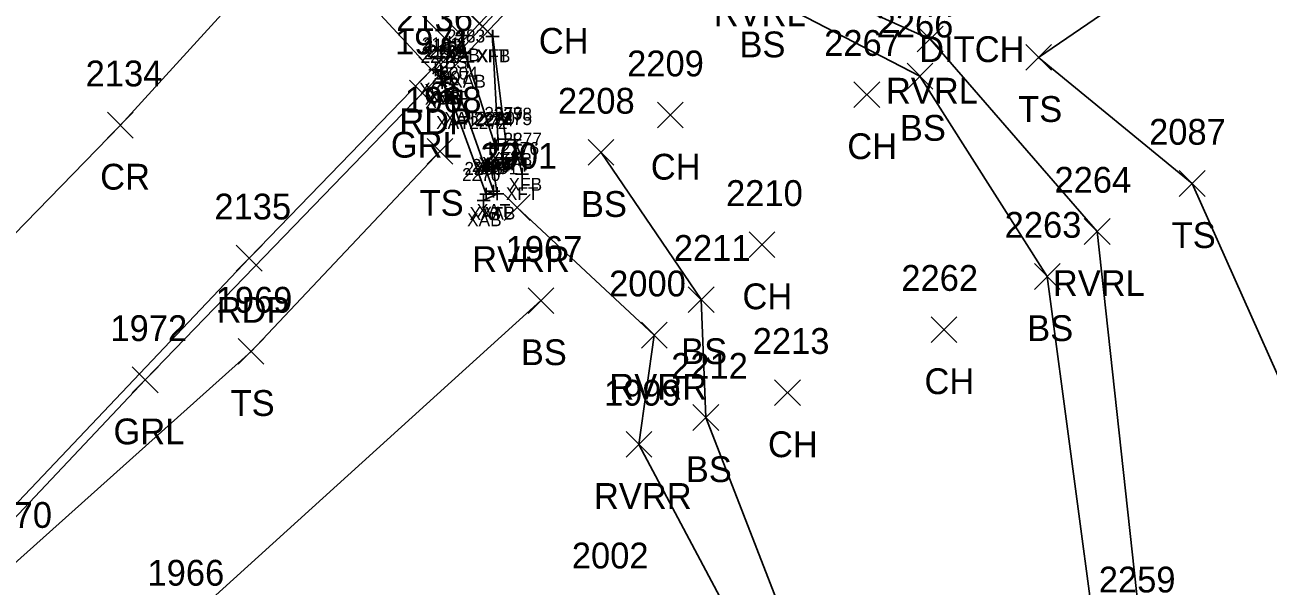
# Model space of a CAD drawing. Extents: x 1633660 to 1636532, y 388643 to 392631.
# Drawn here: x 1634731.9 to 1634828.3, y 389178.4 to 389221.9 of the extents above; entities that cross this region are included whole.
import ezdxf

# ---------------------------------------------------------------- set-up
doc = ezdxf.new("R2010")
doc.units = 0
for name, color, linetype in [('B_A', 7, 'Continuous'), ('B_I', 7, 'Continuous'), ('B_TIC', 7, 'Continuous'), ('BDC', 7, 'Continuous'), ('BFT', 7, 'Continuous'), ('BSE', 7, 'Continuous'), ('BSUBM', 7, 'Continuous'), ('D_A', 7, 'Continuous'), ('L_A', 7, 'Continuous'), ('L_I', 7, 'Continuous'), ('L_TIC', 7, 'Continuous'), ('LAWE', 7, 'Continuous'), ('LELB', 7, 'Continuous'), ('P_A', 7, 'Continuous'), ('P_I', 7, 'Continuous'), ('P_TIC', 7, 'Continuous'), ('PET', 7, 'Continuous'), ('PRC', 7, 'Continuous'), ('R_A', 7, 'Continuous'), ('R_I', 7, 'Continuous'), ('R_TIC', 7, 'Continuous'), ('RGR', 7, 'Continuous')]:
    doc.layers.add(name, color=color, linetype=linetype)

msp = doc.modelspace()

# ---------------------------------------------------------------- linework, layer by layer
at = {"layer": 'B_TIC'}
for p, q in [((1634764.83, 389220.538), (1634764.905, 389220.538)), ((1634765.792, 389221.095), (1634765.867, 389221.095)), ((1634768.164, 389221.033), (1634768.24, 389221.033)), ((1634768.201, 389221.026), (1634768.277, 389221.026)), ((1634763.743, 389218.447), (1634763.818, 389218.447)), ((1634764.167, 389218.344), (1634764.242, 389218.344)), ((1634766.258, 389219.061), (1634766.334, 389219.061)), ((1634764.198, 389217.752), (1634764.273, 389217.752)), ((1634764.265, 389217.48), (1634764.34, 389217.48)), ((1634764.459, 389217.898), (1634764.534, 389217.898)), ((1634764.903, 389217.804), (1634764.979, 389217.804)), ((1634765.097, 389215.857), (1634765.173, 389215.857)), ((1634765.728, 389216.186), (1634765.804, 389216.186)), ((1634768.359, 389212.667), (1634768.434, 389212.667)), ((1634768.466, 389212.553), (1634768.541, 389212.553)), ((1634768.609, 389212.698), (1634768.685, 389212.698)), ((1634769.173, 389213.071), (1634769.249, 389213.071)), ((1634769.889, 389213.007), (1634769.964, 389213.007)), ((1634769.892, 389212.659), (1634769.967, 389212.659)), ((1634767.992, 389212.36), (1634768.067, 389212.36)), ((1634770.659, 389211.073), (1634770.734, 389211.073)), ((1634770.466, 389210.348), (1634770.542, 389210.348)), ((1634767.69, 389208.805), (1634767.766, 389208.805)), ((1634768.245, 389209.038), (1634768.321, 389209.038)), ((1634768.538, 389208.841), (1634768.614, 389208.841)), ((1634767.482, 389208.325), (1634767.558, 389208.325))]:
    msp.add_line(p, q, dxfattribs=at)
for points in [[(1634765.788, 389220.595), (1634765.788, 389221.595)], [(1634768.161, 389220.533), (1634768.161, 389221.533)], [(1634768.198, 389220.526), (1634768.198, 389221.526)], [(1634764.326, 389220.538), (1634765.326, 389220.538)], [(1634764.826, 389220.038), (1634764.826, 389221.038)], [(1634765.288, 389221.095), (1634766.288, 389221.095)], [(1634767.661, 389221.033), (1634768.661, 389221.033)], [(1634767.698, 389221.026), (1634768.698, 389221.026)], [(1634766.255, 389218.561), (1634766.255, 389219.561)], [(1634763.24, 389218.447), (1634764.24, 389218.447)], [(1634763.663, 389218.344), (1634764.663, 389218.344)], [(1634763.74, 389217.947), (1634763.74, 389218.947)], [(1634764.163, 389217.844), (1634764.163, 389218.844)], [(1634764.455, 389217.398), (1634764.455, 389218.398)], [(1634765.755, 389219.061), (1634766.755, 389219.061)], [(1634763.694, 389217.752), (1634764.694, 389217.752)], [(1634763.761, 389217.48), (1634764.761, 389217.48)], [(1634763.955, 389217.898), (1634764.955, 389217.898)], [(1634764.194, 389217.252), (1634764.194, 389218.252)], [(1634764.261, 389216.98), (1634764.261, 389217.98)], [(1634764.4, 389217.804), (1634765.4, 389217.804)], [(1634764.9, 389217.304), (1634764.9, 389218.304)], [(1634765.725, 389215.686), (1634765.725, 389216.686)], [(1634764.594, 389215.857), (1634765.594, 389215.857)], [(1634765.094, 389215.357), (1634765.094, 389216.357)], [(1634765.225, 389216.186), (1634766.225, 389216.186)], [(1634769.17, 389212.571), (1634769.17, 389213.571)], [(1634767.855, 389212.667), (1634768.855, 389212.667)], [(1634767.962, 389212.553), (1634768.962, 389212.553)], [(1634767.988, 389211.86), (1634767.988, 389212.86)], [(1634768.106, 389212.698), (1634769.106, 389212.698)], [(1634768.355, 389212.167), (1634768.355, 389213.167)], [(1634768.462, 389212.053), (1634768.462, 389213.053)], [(1634768.606, 389212.198), (1634768.606, 389213.198)], [(1634768.67, 389213.071), (1634769.67, 389213.071)], [(1634769.385, 389213.007), (1634770.385, 389213.007)], [(1634769.388, 389212.659), (1634770.388, 389212.659)], [(1634769.885, 389212.507), (1634769.885, 389213.507)], [(1634769.888, 389212.158), (1634769.888, 389213.159)], [(1634767.488, 389212.36), (1634768.488, 389212.36)], [(1634770.155, 389211.073), (1634771.155, 389211.073)], [(1634770.463, 389209.848), (1634770.463, 389210.848)], [(1634770.655, 389210.573), (1634770.655, 389211.573)], [(1634769.963, 389210.348), (1634770.963, 389210.348)], [(1634767.187, 389208.805), (1634768.187, 389208.805)], [(1634767.479, 389207.825), (1634767.479, 389208.825)], [(1634767.687, 389208.305), (1634767.687, 389209.305)], [(1634767.742, 389209.038), (1634768.742, 389209.038)], [(1634768.035, 389208.841), (1634769.035, 389208.841)], [(1634768.242, 389208.538), (1634768.242, 389209.538)], [(1634768.535, 389208.341), (1634768.535, 389209.341)], [(1634766.979, 389208.325), (1634767.979, 389208.325)]]:
    msp.add_lwpolyline(points, dxfattribs=at)
at = {"layer": 'BDC'}
for points in [[(1634764.194, 389217.752), (1634763.74, 389218.447), (1634778.837, 389234.337), (1634779.352, 389233.631)], [(1634779.312, 389233.554), (1634778.858, 389234.061), (1634764.163, 389218.344), (1634764.455, 389217.898)], [(1634764.455, 389217.898), (1634779.312, 389233.554)]]:
    msp.add_lwpolyline(points, dxfattribs=at)
at = {"layer": 'BFT'}
for points in [[(1634746.993, 389241.835), (1634768.161, 389221.033)], [(1634747.068, 389242.136), (1634768.198, 389221.026)], [(1634768.606, 389212.698), (1634768.161, 389221.033)], [(1634770.655, 389211.073), (1634769.885, 389213.007), (1634769.17, 389213.071), (1634768.198, 389221.026)], [(1634768.462, 389212.553), (1634769.888, 389212.659), (1634770.463, 389210.348)]]:
    msp.add_lwpolyline(points, dxfattribs=at)
at = {"layer": 'BSE'}
msp.add_lwpolyline([(1634764.826, 389220.538), (1634746.059, 389239.297), (1634742.923, 389241.263)], dxfattribs=at)
at = {"layer": 'BSUBM'}
for points in [[(1634728.916, 389249.02), (1634729.836, 389250.104), (1634742.136, 389242.622), (1634746.673, 389240.04), (1634765.788, 389221.095)], [(1634765.788, 389221.095), (1634766.255, 389219.061)], [(1634767.479, 389208.325), (1634768.535, 389208.841), (1634767.988, 389212.36), (1634768.355, 389212.667), (1634766.255, 389219.061)], [(1634764.261, 389217.48), (1634764.9, 389217.804), (1634765.725, 389216.186), (1634768.242, 389209.038), (1634767.687, 389208.805), (1634765.094, 389215.857)], [(1634765.094, 389215.857), (1634764.261, 389217.48)]]:
    msp.add_lwpolyline(points, dxfattribs=at)
at = {"layer": 'L_TIC'}
for points in [[(1634801.108, 389219.823), (1634803.108, 389221.823)], [(1634803.108, 389219.823), (1634801.108, 389221.823)], [(1634809.516, 389218.404), (1634811.516, 389220.404)], [(1634811.516, 389218.404), (1634809.516, 389220.404)], [(1634800.315, 389216.947), (1634802.315, 389218.947)], [(1634802.315, 389216.947), (1634800.315, 389218.947)], [(1634796.191, 389215.523), (1634798.191, 389217.523)], [(1634798.191, 389215.523), (1634796.191, 389217.523)], [(1634780.954, 389213.935), (1634782.954, 389215.935)], [(1634782.954, 389213.935), (1634780.954, 389215.935)], [(1634763.106, 389211.132), (1634765.106, 389213.132)], [(1634765.106, 389211.132), (1634763.106, 389213.132)], [(1634775.585, 389211.045), (1634777.585, 389213.045)], [(1634777.585, 389211.045), (1634775.585, 389213.045)], [(1634821.419, 389208.639), (1634823.419, 389210.639)], [(1634823.419, 389208.639), (1634821.419, 389210.639)], [(1634769.084, 389206.774), (1634771.084, 389208.774)], [(1634771.084, 389206.774), (1634769.084, 389208.774)], [(1634814.049, 389204.919), (1634816.049, 389206.919)], [(1634816.049, 389204.919), (1634814.049, 389206.919)], [(1634788.059, 389203.893), (1634790.059, 389205.893)], [(1634790.059, 389203.893), (1634788.059, 389205.893)], [(1634810.187, 389201.43), (1634812.187, 389203.43)], [(1634812.187, 389201.43), (1634810.187, 389203.43)], [(1634770.923, 389199.563), (1634772.923, 389201.563)], [(1634772.923, 389199.563), (1634770.923, 389201.563)], [(1634783.352, 389199.641), (1634785.352, 389201.641)], [(1634785.352, 389199.641), (1634783.352, 389201.641)], [(1634802.174, 389197.318), (1634804.174, 389199.318)], [(1634804.174, 389197.318), (1634802.174, 389199.318)], [(1634779.716, 389196.887), (1634781.716, 389198.887)], [(1634781.716, 389196.887), (1634779.716, 389198.887)], [(1634748.452, 389195.628), (1634750.452, 389197.628)], [(1634750.452, 389195.628), (1634748.452, 389197.628)], [(1634790.04, 389192.433), (1634792.04, 389194.433)], [(1634792.04, 389192.433), (1634790.04, 389194.433)], [(1634783.715, 389190.503), (1634785.715, 389192.503)], [(1634785.715, 389190.503), (1634783.715, 389192.503)], [(1634778.524, 389188.425), (1634780.524, 389190.425)], [(1634780.524, 389188.425), (1634778.524, 389190.425)]]:
    msp.add_lwpolyline(points, dxfattribs=at)
at = {"layer": 'LAWE'}
for points in [[(1634485.266, 388945.868), (1634504.196, 388941.237), (1634525.532, 388940.734), (1634548.507, 388932.941), (1634584.664, 388919.999), (1634598.752, 388914.409), (1634618.803, 388928.878), (1634638.301, 388944.913), (1634660.99, 388957.079), (1634677.576, 388983.238), (1634696.949, 389006.397), (1634707.364, 389033.308), (1634727.928, 389056.715), (1634749.887, 389078.696), (1634762.92, 389095.064), (1634797.897, 389102.54), (1634816.332, 389112.037), (1634824.178, 389130.773), (1634824.184, 389150.648), (1634818.446, 389174.952), (1634815.049, 389205.919), (1634802.108, 389220.823), (1634788.756, 389226.818)], [(1634520.427, 388972.828), (1634529.584, 388972.39), (1634557.271, 388957.371), (1634580.073, 388955.673), (1634596.477, 388954.834), (1634611.771, 388964.288), (1634628.481, 388986.245), (1634647.884, 389006.905), (1634658.845, 389024.296), (1634672.697, 389044.328), (1634690.555, 389064.603), (1634720.634, 389097.891), (1634743.803, 389121.879), (1634765.955, 389139.813), (1634789.876, 389159.93), (1634790.778, 389168.232), (1634779.524, 389189.425), (1634780.716, 389197.887), (1634770.084, 389207.774)]]:
    msp.add_lwpolyline(points, dxfattribs=at)
at = {"layer": 'LELB'}
for points in [[(1634837.414, 389240.465), (1634826.209, 389230.13), (1634810.516, 389219.404), (1634822.419, 389209.639), (1634833.611, 389184.58), (1634846.556, 389159.137)], [(1634633.695, 388947.021), (1634652.585, 388956.595), (1634671.201, 388984.135), (1634685.401, 389000.206), (1634693.628, 389014.81), (1634704.343, 389035.4), (1634725.63, 389062.246), (1634746.904, 389081.237), (1634759.284, 389096.885), (1634788.685, 389102.007), (1634810.124, 389114.596), (1634818.922, 389123.639), (1634818.088, 389148.686), (1634815.048, 389173.408), (1634811.187, 389202.43), (1634801.315, 389217.947), (1634788.875, 389224.41)], [(1634776.585, 389212.045), (1634784.352, 389200.641), (1634784.715, 389191.503), (1634794.509, 389166.297), (1634783.973, 389147.591), (1634762.827, 389128.667), (1634740.891, 389107.131), (1634715.467, 389080.901), (1634695.423, 389057.672), (1634668.321, 389027.162), (1634645.642, 388997.184), (1634619.547, 388957.691)], [(1634764.106, 389212.132), (1634749.452, 389196.628), (1634730.844, 389179.956)], [(1634531.181, 388975.284), (1634550.036, 388993.836), (1634582.852, 389016.577), (1634590.994, 389033.592), (1634624.255, 389062.773), (1634653.379, 389090.437), (1634686.401, 389120.704), (1634717.265, 389150.249), (1634744.215, 389175.478), (1634771.923, 389200.563)]]:
    msp.add_lwpolyline(points, dxfattribs=at)
at = {"layer": 'P_TIC'}
for points in [[(1634762.452, 389217.449), (1634764.452, 389219.449)], [(1634764.452, 389217.449), (1634762.452, 389219.449)], [(1634738.317, 389213.16), (1634740.317, 389215.16)], [(1634740.317, 389213.16), (1634738.317, 389215.16)], [(1634748.297, 389202.848), (1634750.297, 389204.848)], [(1634750.297, 389202.848), (1634748.297, 389204.848)]]:
    msp.add_lwpolyline(points, dxfattribs=at)
at = {"layer": 'PET'}
msp.add_lwpolyline([(1634682.082, 389181.099), (1634650.696, 389146.378), (1634620.246, 389115.231), (1634604.629, 389098.298), (1634579.097, 389070.12), (1634546.556, 389039.303), (1634509.68, 389006.458), (1634474.107, 388976.774), (1634488.61, 388975.178), (1634504.361, 388973.036), (1634532.027, 388994.362), (1634563.211, 389020.041), (1634596.335, 389051.022), (1634641.933, 389096.55), (1634679.614, 389135.055), (1634705.94, 389161.603), (1634722.451, 389175.585), (1634749.297, 389203.848), (1634763.452, 389218.449), (1634753.185, 389229.521), (1634742.756, 389239.644), (1634704.358, 389200.187), (1634691.629, 389189.006)], dxfattribs=at)
at = {"layer": 'PRC'}
msp.add_lwpolyline([(1634489.589, 388976.111), (1634524.497, 389003.937), (1634553.651, 389029.267), (1634589.65, 389062.971), (1634628.748, 389101.269), (1634671.28, 389144.583), (1634699.51, 389173.358), (1634712.637, 389186.748), (1634739.317, 389214.16), (1634752.843, 389228.985)], dxfattribs=at)
at = {"layer": 'R_TIC'}
for points in [[(1634761.739, 389215.637), (1634763.739, 389217.637)], [(1634763.739, 389215.637), (1634761.739, 389217.637)], [(1634740.236, 389193.428), (1634742.236, 389195.428)], [(1634742.236, 389193.428), (1634740.236, 389195.428)]]:
    msp.add_lwpolyline(points, dxfattribs=at)
at = {"layer": 'RGR'}
msp.add_lwpolyline([(1634762.739, 389216.637), (1634741.236, 389194.428), (1634716.388, 389168.134), (1634709.539, 389158.775), (1634705.452, 389150.066)], dxfattribs=at)

# ---------------------------------------------------------------- texts
at = {"layer": 'B_A'}
for s, p in [('XBS', (1634763.566, 389218.538)), ('XAB', (1634764.509, 389219.095)), ('XFT', (1634766.905, 389219.033)), ('XFB', (1634766.958, 389219.026)), ('XCB', (1634762.476, 389216.447)), ('XAB', (1634764.975, 389217.061)), ('XCT', (1634762.884, 389216.344)), ('XCB', (1634762.93, 389215.752)), ('XAT', (1634762.966, 389215.48)), ('XCT', (1634763.176, 389215.898)), ('XAT', (1634763.604, 389215.804)), ('XAT', (1634763.798, 389213.857)), ('XAT', (1634764.43, 389214.186)), ('XAB', (1634767.076, 389210.667)), ('XFT', (1634767.35, 389210.698)), ('XFB', (1634767.93, 389211.071)), ('XFT', (1634768.632, 389210.659)), ('XFB', (1634768.645, 389211.007)), ('XAB', (1634766.709, 389210.36)), ('XFT', (1634767.206, 389210.553)), ('XFB', (1634769.415, 389209.073)), ('XFT', (1634769.207, 389208.348)), ('XAT', (1634766.391, 389206.805)), ('XAT', (1634766.947, 389207.038)), ('XAB', (1634767.255, 389206.841)), ('XAB', (1634766.199, 389206.325))]:
    msp.add_text(s, height=1, dxfattribs=at).set_placement(p)
at = {"layer": 'B_I'}
for s, p in [('2283', (1634764.625, 389220.561)), ('2191', (1634762.677, 389219.947)), ('2190', (1634762.804, 389219.252)), ('2188', (1634762.817, 389219.844)), ('2189', (1634763.105, 389219.398)), ('2203', (1634763.23, 389219.304)), ('2202', (1634762.592, 389218.98)), ('2207', (1634763.424, 389217.357)), ('2204', (1634764.056, 389217.686)), ('2279', (1634767.536, 389214.571)), ('2278', (1634768.256, 389214.507)), ('2272', (1634766.359, 389213.86)), ('2273', (1634766.725, 389214.167)), ('2274', (1634766.832, 389214.053)), ('2280', (1634766.933, 389214.198)), ('2275', (1634768.258, 389214.159)), ('2277', (1634769.025, 389212.573)), ('2276', (1634768.805, 389211.848)), ('2270', (1634765.805, 389209.825)), ('2206', (1634765.99, 389210.305)), ('2205', (1634766.573, 389210.538)), ('2271', (1634767.188, 389210.341))]:
    msp.add_text(s, height=1, dxfattribs=at).set_placement(p)
at = {"layer": 'D_A'}
msp.add_text('DITCH', height=2, dxfattribs=at).set_placement((1634801.249, 389219.04))
at = {"layer": 'L_A'}
for s, p in [('RVRL', (1634785.323, 389221.818)), ('CH', (1634771.758, 389219.69)), ('BS', (1634787.316, 389219.41)), ('RVRL', (1634798.675, 389215.823)), ('TS', (1634808.926, 389214.404)), ('BS', (1634799.756, 389212.947)), ('CH', (1634795.679, 389211.523)), ('CH', (1634780.442, 389209.935)), ('TS', (1634762.516, 389207.132)), ('BS', (1634775.026, 389207.045)), ('TS', (1634820.828, 389204.639)), ('RVRR', (1634766.595, 389202.774)), ('RVRL', (1634811.616, 389200.919)), ('CH', (1634787.548, 389199.893)), ('BS', (1634809.628, 389197.43)), ('BS', (1634770.364, 389195.563)), ('BS', (1634782.793, 389195.641)), ('CH', (1634801.662, 389193.318)), ('RVRR', (1634777.228, 389192.887)), ('TS', (1634747.862, 389191.628)), ('CH', (1634789.528, 389188.433)), ('BS', (1634783.156, 389186.503)), ('RVRR', (1634776.035, 389184.425))]:
    msp.add_text(s, height=2, dxfattribs=at).set_placement(p)
at = {"layer": 'L_I'}
for s, p in [('2266', (1634797.953, 389220.947)), ('2267', (1634793.884, 389219.523)), ('2209', (1634778.607, 389217.935)), ('1968', (1634761.366, 389215.132)), ('2208', (1634773.246, 389215.045)), ('2087', (1634819.08, 389212.639)), ('2001', (1634767.233, 389210.774)), ('2264', (1634811.742, 389208.919)), ('2210', (1634786.28, 389207.893)), ('2263', (1634807.88, 389205.43)), ('1967', (1634769.183, 389203.563)), ('2211', (1634782.226, 389203.641)), ('2000', (1634777.212, 389200.887)), ('2262', (1634799.866, 389201.318)), ('1969', (1634746.704, 389199.628)), ('2213', (1634788.347, 389196.433)), ('2212', (1634782.022, 389194.503)), ('1999', (1634776.823, 389192.425)), ('1970', (1634728.065, 389182.956)), ('2002', (1634774.319, 389179.811)), ('1966', (1634741.419, 389178.478)), ('2259', (1634815.179, 389177.952))]:
    msp.add_text(s, height=2, dxfattribs=at).set_placement(p)
at = {"layer": 'P_A'}
for s, p in [('RDP', (1634760.941, 389213.449)), ('CR', (1634737.75, 389209.16)), ('RDP', (1634746.785, 389198.848))]:
    msp.add_text(s, height=2, dxfattribs=at).set_placement(p)
at = {"layer": 'P_I'}
for s, p in [('2136', (1634760.704, 389221.449)), ('2134', (1634736.624, 389217.16)), ('2135', (1634746.604, 389206.848))]:
    msp.add_text(s, height=2, dxfattribs=at).set_placement(p)
at = {"layer": 'R_A'}
for p in [(1634760.282, 389211.637), (1634738.779, 389189.428)]:
    msp.add_text('GRL', height=2, dxfattribs=at).set_placement(p)
at = {"layer": 'R_I'}
for s, p in [('1971', (1634760.613, 389219.637)), ('1972', (1634738.543, 389197.428))]:
    msp.add_text(s, height=2, dxfattribs=at).set_placement(p)

doc.saveas('drawing.dxf')
